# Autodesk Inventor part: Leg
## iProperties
Created: 2010-08
Part Number: Leg
Material: Default
Document SubType Name: Modeling
Designer: Paul Munford
Density: 1 g/cm^3
Author: Paul Munford
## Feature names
1. TaggingFeature2
